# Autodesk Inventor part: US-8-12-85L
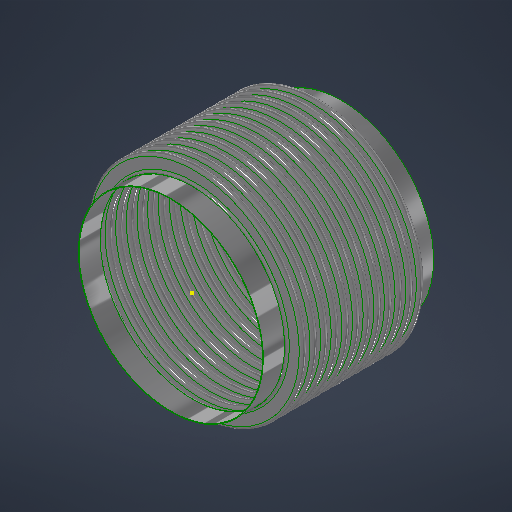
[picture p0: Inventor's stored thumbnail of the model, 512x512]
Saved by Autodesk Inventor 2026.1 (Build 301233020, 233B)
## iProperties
Category: 22 GA (0.030 THICK)
RuleStatus: InUse
Created: 2026-07
Part Number: US-8-12-85L
Project: =STOCK BELLOWS: <Stock Number><SFILL>
Material: ASTM A240-304
Description: =STOCK BELLOWS: <Stock Number>, <SID_> I.D., <SOD_> O.D., <SPLY_> PLY, <Category>, <SNET_CONS> CONS.<PITCH_><STANGENT_> TANGENT<SFILL>
Document SubType Name: Sheet Metal
Designer: LC
Stock Number: U.S-8-12-85L
Surface Area: 659.127 cm^2
Volume: 56.61 cm^3
Sheet Metal Rule: Default
Appearance: STAINLESS STEEL
NET_TUBE: 3.428
COUNTER: 1.500
PBAR: 1.214
PSET: 5.356
PLY: 2
CONS: 2
THK: 0.036
ID: 4.500
OD: 5.500
CONS_: 2
TANGENT: 0.500
PITCH: 0.375
BELLOWS_UPSET: 0.000
NET_CONS: 2
S_CONS: 0
Description_Units: 0
ID_M: 114.30 mm
OD_M: 139.70 mm
THK_M: 0.91 mm
ID_U: 4.500 in
OD_U: 5.500 in
THK_U: 0.036 in
TANGENT2: 0.500
d79: 1.000
d82: 1.000
d83: 26.000
d84: 24.000
d80: 2.571
d81: 10
SID: 2.375
SCONS_: 12
SPITCH: 0.250
SBELLOWS_UPSET: 0.000
SNET_CONS: 12
SS_CONS: 0
SCONS: 8
d174: 8
d177: 0.018
d178: 2.375
d179: 3.000
d180: 0.375
d181: 1.000
d182: 0.000
d190: 8
d191: 1
d192: 1
d193: 8
d194: 0
PART_NUMBER: U.S-8-12-85L
PRESSURE: 85
SIZE: 8.00
STANGENT_: 1.000
d214: 8
d217: 0.030
d218: 6.625
d219: 8.125
d220: 0.500
d221: 1.000
d222: 0.000
d230: 8
d231: 1
d232: 1
d233: 8
d234: 0
STANGENT: 4.000
SPLY_: 1
STHK_: 0.030
SID_: 8.625
SOD_: 10.125
SPITCH_: 0.500
STANGENT__: 1.000
SBELLOWS_UPSET_: 0.000
SDIFF_TAN: 1.000
TAN_TO_TAN: 0.750 in
d252: 2
d275: 2
d287: 0.050
d289: 0.500
d290: 0.000
d263: 2
d265: 1
d268: 2
d269: 0
d286: 2
d288: 1
d291: 2
d292: 0
SOD_NECK: 8 11/16
CFILL: .
SFILL: .
PITCH_: =, <SPITCH_> PITCH,
SREROLL: 0.750
MATTABLE: 20 GA (0.036 THICK)
MESH: ,
CSECT: 2
Author: LC
Keywords: 20 GA (0.036 THICK)
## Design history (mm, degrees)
sketch "Sketch2"
  geometry: L1 (0, -183.595)-(0, 600.956) reference; L2 (58.979, 0)-(57.15, 0); L3 (60.446, -1.467)-(66.554, -1.467); L4 (60.446, -3.296)-(66.554, -3.296); L5 (66.554, -8.058)-(60.446, -8.058); L6 (66.554, -6.229)-(60.446, -6.229); L7 (58.979, -9.525)-(57.15, -9.525); L8 (60.446, 0)-(60.446, -9.525); L9 (66.554, -4.762)-(69.85, -4.763); L10 (57.15, 0)-(57.15, -9.525); L11 (20.376, 102.841)-(20.376, 101.926); L12 (58.262, 488.877)-(58.262, 349.177); L13 (58.262, 479.352)-(58.262, 339.652); L14 (93.133, -58.817)-(93.133, -71.517); L15 (118.746, -66.401)-(118.746, -66.401); L16 (66.554, -6.229)-(66.554, -8.058); L17 (60.446, -6.229)-(60.446, -8.058); L18 (60.446, -7.144)-(66.554, -7.144); L19 (69.85, 0)-(69.85, -9.525); L20 (-66.554, -6.229)-(-66.554, -8.058); L21 (-66.554, -1.467)-(-60.446, -1.467); L22 (-66.554, -3.296)-(-60.446, -3.296); L23 (-60.446, -6.229)-(-66.554, -6.229); L24 (-66.554, -7.144)-(-60.446, -7.144); L25 (-60.446, -8.058)-(-66.554, -8.058); L26 (-60.446, -6.229)-(-60.446, -8.058); L27 (-57.15, -2.522)-(-57.15, -12.047); L28 (-60.446, -4.763)-(-57.15, -4.763); L29 (-66.554, 3.828)-(-66.554, -9.525); L30 (-68.021, 0)-(-69.85, 0); L31 (-69.85, 0)-(-69.85, -9.525); L32 (-68.021, -9.525)-(-69.85, -9.525); A1 r 1.467 centre (60.446, 0) between (58.979, 0) and (60.446, -1.467); A2 r 3.296 centre (60.446, 0) between (57.15, 0) and (60.446, -3.296); A3 r 3.296 centre (66.554, -4.762) between (66.554, -8.058) and (66.554, -1.467); A4 r 1.467 centre (66.554, -4.762) between (66.554, -6.229) and (66.554, -3.296); A5 r 1.467 centre (60.446, -9.525) between (60.446, -8.058) and (58.979, -9.525); A6 r 3.296 centre (60.446, -9.525) between (60.446, -6.229) and (57.15, -9.525); A7 r 2.381 centre (66.554, -4.762) between (66.554, -7.144) and (68.936, -4.762); A8 r 2.381 centre (60.446, -9.525) between (60.446, -7.144) and (58.064, -9.525); A9 r 1.467 centre (-66.554, -9.525) between (-66.554, -8.058) and (-68.021, -9.525); A10 r 1.467 centre (-60.446, -4.763) between (-60.446, -6.229) and (-60.446, -3.296); A11 r 2.381 centre (-60.446, -4.763) between (-60.446, -7.144) and (-58.064, -4.763); A12 r 3.296 centre (-60.446, -4.763) between (-60.446, -8.058) and (-60.446, -1.467); A13 r 2.381 centre (-66.554, -9.525) between (-66.554, -7.144) and (-68.936, -9.525); A14 r 3.296 centre (-66.554, -9.525) between (-66.554, -6.229) and (-69.85, -9.525); A15 r 1.467 centre (-66.554, 0) between (-68.021, 0) and (-66.554, -1.467); A16 r 3.296 centre (-66.554, 0) between (-69.85, 0) and (-66.554, -3.296); 10 further points
  constraints: 62 end point, 38 point on circle, 20 tangent, 16 centre point, 12 parallel, 9 midpoint, 7 vertical, 6 coincident, 6 concentric, 6 point on line, 4 equal radius, 4 perpendicular, 3 horizontal, 1 collinear, 1 horizontal alignment, 10 other
  dimensions: "THK" = 0.9144 distance of L11.start L11.end; "ID" = 114.3 distance of L11.end point (20.376, -12.374); "OD" = 139.7 distance of L12.start L12.end; "PITCH" = 9.525 distance of L12.start L13.start; "TANGENT" = 12.7 distance of L14.start L14.end; "BELLOWS_UPSET" = 0 distance of L15.start L15.end; "d43" = 114.3 diameter of L10 L1 (= ID); "d44" = 139.7 diameter of L9.end L1 (= OD); "d45" = 1.8288 distance between parallel lines of L5 L6 (computed from THK, PLY); "d46" = 3.29565 radius of A3 (computed from PITCH, THK, PLY); "UPSET_PITCH" = 9.525 distance of L2.end L7.end (derived); "SIDEWALL_ANGLE" = 0 deg angle of L3 L9 (derived); "CON_GAP" = 2.9337 distance of point (60.446, -6.229) point (60.446, -3.296) (derived); "TAN1" = 3.74046 dimension on A8 (derived); "TAN2" = 3.74046 dimension on A7 (derived); "LEG1" = 6.1087 distance of L18.start L18.end (derived); "d278" = 1.8288 distance between parallel lines of L25 L23 (derived); "d279" = 3.29565 radius of A12 (derived); "d280" = 9.525 distance of L30.end L31.end (derived); "d281" = 360 deg dimension on L21 L28 (derived); "d282" = 2.9337 distance of point (-66.554, -6.229) point (-66.554, -3.296) (derived); "d283" = 3.74046 dimension on A13 (derived); "d284" = 3.74046 dimension on A11 (derived); "d285" = 6.1087 distance of L24.start L24.end (derived); "d293" = 114.3 diameter of L27 L1 (derived); "d294" = 139.7 diameter of L31 L1 (derived)
  node "Sketch Rectangular Pattern1" dims "d31" = 25.4, "ID" = 114.3
  node "Sketch Rectangular Pattern2" dims "d39" = 25.4, "PITCH" = 9.525
revolve "CONS" stored, may be unused: angle "d48" = 90 deg
node "BELLOW MIDPLANE"
pattern_linear "Rectangular Pattern2" dims "d52" = 9.525 (= UPSET_PITCH)
sketch "Sketch5"
  geometry: C1 r 58.979 at (0, 0) reference; C2 r 57.15 at (0, 0) reference
extrude "TANGENT" new body sketch "Sketch5" distance "d53" = 12.7 (= TANGENT); taper "d54" = 0 deg
revolve "SAMETAN" stored, may be unused: angle "d65" = 90 deg
revolve "DIFFTAN" stored, may be unused: angle "d70" = 90 deg
sketch "Sketch9"
  geometry: L1 (58.391, 0)-(-58.391, 0) reference; L2 (0, -17.78)-(0, 17.78) reference; L3 (41.708, 0)-(-41.708, 0); L4 (41.708, -11.906)-(41.708, 11.906); L5 (29.008, -11.906)-(29.008, 11.906); L6 (15.418, 11.906)-(15.418, -11.906); L7 (-29.008, -11.906)-(-29.008, 11.906); L8 (-41.708, -11.906)-(-41.708, 11.906); L9 (40.914, -11.906)-(40.914, 11.906); L10 (41.708, -11.906)-(40.914, -11.906); L11 (41.708, 11.906)-(40.914, 11.906); L12 (15.815, 11.906)-(15.022, 11.906); L13 (15.022, 11.906)-(15.022, -11.906); L14 (15.022, -11.906)-(15.815, -11.906); L15 (15.815, -11.906)-(15.815, 11.906); L16 (-15.815, 11.906)-(-15.815, -11.906); L17 (-15.418, 11.906)-(-15.418, -11.906); L18 (-15.815, -11.906)-(-15.022, -11.906); L19 (-15.022, -11.906)-(-15.022, 11.906); L20 (-15.022, 11.906)-(-15.815, 11.906); L21 (-41.708, -11.906)-(-40.914, -11.906); L22 (-40.914, -11.906)-(-40.914, 11.906); L23 (-40.914, 11.906)-(-41.708, 11.906); L24 (-41.708, 11.906)-(-41.708, -11.906); L25 (41.708, -0.397)-(-41.708, -0.397); L26 (-41.708, -0.397)-(-41.708, 0.397); L27 (-41.708, 0.397)-(41.708, 0.397); L28 (41.708, 0.397)-(41.708, -0.397); L29 (-41.708, 11.906)-(41.708, 11.906); L30 (41.708, 11.906)-(41.708, 12.7); L31 (41.708, 12.7)-(-41.708, 12.7); L32 (-41.708, 12.7)-(-41.708, 11.906); L33 (41.708, -11.906)-(-41.708, -11.906); L34 (-41.708, -11.906)-(-41.708, -12.7); L35 (-41.708, -12.7)-(41.708, -12.7); L36 (41.708, -12.7)-(41.708, -11.906); 30 further points
  constraints: 68 end point, 13 midpoint, 13 parallel, 8 horizontal, 7 perpendicular, 6 equal length, 3 point on line, 2 vertical, 14 other
  dimensions: "d115" = 23.8125 distance of L4.start L4.end (derived); "d116" = 12.7 distance between parallel lines of L4 L5 (derived); "d117" = 13.58962 distance between parallel lines of L5 L6 (derived); "d125" = 44.42645 distance between parallel lines of L7 L6 (derived); "d127" = 12.7 distance between parallel lines of L8 L7 (derived); "d128" = 26.28962 distance between parallel lines of L6 L4 (derived); "d130" = 83.41607 distance between parallel lines of L8 L4 (derived); "RULER_THK" = 0.79375 distance between parallel lines of L4 L9; "d135" = 0.79375 distance of L13.end L14.end (derived); "d138" = 30.83684 distance of L13.end L16.end (derived); "d143" = 0.79375 distance of L22.end L8.end (derived); "d144" = 0.79375 distance between parallel lines of L27 L25 (derived)
extrude "RULER" join sketch "Sketch9" distance "d149" = 0.79375 (derived); taper "d150" = 0 deg
extrude "BARS" join sketch "Sketch9" distance "d151" = 0.79375 (derived); taper "d152" = 0 deg
pattern_linear "Rectangular Pattern4" dims "d155" = 30.83684 (derived)
sketch "Sketch13"
  geometry: L1 (93.149, -52.467)-(93.149, -77.867); L2 (110.299, 0)-(109.537, 0); L3 (110.299, -12.7)-(109.537, -12.7); L4 (125.031, -9.906)-(113.093, -9.906); L5 (125.032, -9.144)-(113.094, -9.144); L6 (125.031, -6.35)-(128.588, -6.35); L7 (113.094, -2.794)-(125.031, -2.794); L8 (113.094, 0)-(113.093, -12.7); L9 (109.537, 0)-(109.537, -12.7); L10 (58.254, -312.281)-(58.254, -569.456); L11 (58.254, -324.981)-(58.254, -582.156); L12 (58.254, -350.381)-(58.254, -607.556); L13 (58.254, -363.081)-(58.254, -620.256); L14 (58.254, -375.781)-(58.254, -632.956); L15 (58.254, -388.481)-(58.254, -645.656); L16 (58.254, -401.181)-(58.254, -658.356); L17 (58.254, -337.681)-(58.254, -594.856); L18 (20.376, 102.688)-(20.376, 101.926); L19 (113.094, -3.556)-(125.031, -3.556); L20 (0, -769.925)-(0, 248.124) reference; L21 (-23.752, 0)-(142.514, 0) reference; A1 r 2.794 centre (113.094, 0) between (110.299, 0) and (113.094, -2.794); A2 r 2.794 centre (113.093, -12.7) between (113.093, -9.906) and (110.299, -12.7); A3 r 3.556 centre (113.093, -12.7) between (113.094, -9.144) and (109.537, -12.7); A4 r 2.794 centre (125.031, -6.35) between (125.032, -9.144) and (125.031, -3.556); A5 r 3.556 centre (125.031, -6.35) between (125.031, -9.906) and (125.031, -2.794); A6 r 3.556 centre (113.094, 0) between (109.537, 0) and (113.094, -3.556); 6 further points; 1 other entity
  constraints: 38 end point, 15 point on circle, 9 tangent, 6 centre point, 6 parallel, 5 vertical alignment, 4 point on line, 4 vertical, 3 coincident, 3 concentric, 2 collinear, 2 equal radius, 1 horizontal, 1 perpendicular, 23 other
  dimensions: "SBELLOWS_UPSET_" = 0 distance of point (118.762, -66.401) point (118.762, -66.401); "STOTAL_THK_BELLOW__" = 0.762 distance between parallel lines of L4 L5 (derived); "d224" = 3.556 radius of A5 (derived); "d225" = 12.7 distance of L2.end L3.end (derived); "SSIDEWALL_ANGLE_" = 0 deg angle of L7 L6 (derived); "SSCON_GAP_" = 5.588 distance of point (113.094, -9.144) point (113.094, -3.556) (derived); "d235" = 219.075 diameter of L9 L20 (derived); "d236" = 257.175 diameter of L6.end L20 (derived)
  node "Sketch Rectangular Pattern4" dims "d228" = 25.4
  node "Sketch Rectangular Pattern5" dims "d229" = 25.4
revolve "SBELLOW" stored, may be unused: angle "d197" = 90 deg
pattern_linear "Rectangular Pattern5" dims "d204" = 12.7 (derived)
revolve "STANGENT" stored, may be unused: angle "d240" = 90 deg
revolve "SSAMETAN" stored, may be unused: angle "d241" = 90 deg
revolve "SDIFFTAN" stored, may be unused: angle "d246" = 90 deg
revolve "INVCON" stored, may be unused: angle "d295" = 90 deg
pattern_linear "Rectangular Pattern6" dims "d298" = 9.525 (derived)
revolve "INVTANGENT" stored, may be unused: angle "d302" = 90 deg
revolve "INVSAMETAN" stored, may be unused: angle "d307" = 90 deg
revolve "INVDIFFTAN" stored, may be unused: angle "d312" = 90 deg
sketch "ID BELLOW MOUNT CALC"
  geometry: L1 (44.45, 0)-(38.1, 0); L2 (38.1, 0)-(38.1, 12.7); L3 (38.1, 12.7)-(44.45, 12.7); L4 (44.45, 12.7)-(44.45, 0); L5 (36.513, 12.7)-(34.684, 12.7); L6 (34.684, 12.7)-(34.684, 0); L7 (34.684, 0)-(36.513, 0); L8 (36.513, 0)-(36.513, 12.7); L9 (0, -2.54)-(0, 15.24) reference; L10 (-8.89, 0)-(53.34, 0) reference; 1 further point
  constraints: 16 end point, 5 parallel, 2 collinear, 2 horizontal, 2 perpendicular
  dimensions: "d314" = 12.7 distance of L5.end L6.end (derived); "d315" = 1.8288 distance of L5.start L5.end (derived); "IG" = 1.5875 distance between parallel lines of L2 L8; "PIPE_OD" = 88.9 diameter of L4 L9; "PIPE_WALL" = 6.35 distance of L2.end L3.end; "ID_MT_BELLOW" = 69.3674 diameter of L6 L9 (derived)
revolve "CFILL" stored, may be unused: angle "d320" = 90 deg
pattern_linear "Rectangular Pattern7" dims "d323" = 9.525 (derived)
revolve "SFILL" stored, may be unused: angle "d324" = 90 deg
pattern_linear "Rectangular Pattern8" dims "d327" = 12.7 (derived)
node "STOCK BELLOW MIDPLANE"
sketch "Sketch21"
  geometry: L1 (0, -100.013)-(0, 100.013) reference; L2 (-100.013, 0)-(100.013, 0) reference; L3 (-0.099, 71.437)-(0.099, 71.437); L4 (0.099, 71.437)-(0.099, 55.562); L5 (0.099, 55.562)-(-0.099, 55.562); L6 (-0.099, 55.562)-(-0.099, 71.437); C1 r 55.562 at (0, 0); C2 r 71.437 at (0, 0); 3 further points
  constraints: 8 end point, 2 centre point, 2 coincident, 2 parallel, 2 tangent, 1 horizontal, 1 perpendicular, 1 other
  dimensions: "d329" = 111.125 diameter of C1 (derived); "d330" = 142.875 diameter of C2 (derived); "d331" = 0.19844 distance of L3.start L3.end
extrude "CLAMSHELL" cut sketch "Sketch21" extent not by distance; stored distance "d332" = 0; taper "d333" = 0 deg
pattern_circular "Circular Pattern1" dims angle "d335" = 180 deg (derived)
node "BELLOW"
sketch "Sketch6"
  geometry: L1 (-19.05, 58.979)-(-6.35, 58.979); L2 (-6.35, 58.979)-(-6.35, 57.15); L3 (-6.35, 57.15)-(-19.05, 57.15); L4 (-19.05, 57.15)-(-19.05, 58.979); L5 (2.54, 0)-(-59.69, 0) reference; L6 (-38.1, -108.388)-(-38.1, 156.601) reference; 1 further point
  constraints: 8 end point, 2 parallel, 1 horizontal, 1 perpendicular
  dimensions: "d61" = 12.7 distance of L2.end L3.end (derived); "d62" = 1.8288 distance of L1.end L2.end (derived); "d63" = 114.3 diameter of L3 L5 (derived); "d64" = 19.05 distance between parallel lines of L4 L6 (derived)
sketch "Sketch12"
  geometry: 1 further point
sketch "Sketch14"
  geometry: L1 (-25.4, 110.299)-(0, 110.299); L2 (0, 110.299)-(0, 109.537); L3 (0, 109.537)-(-25.4, 109.537); L4 (-25.4, 109.537)-(-25.4, 110.299); L5 (5.08, 0)-(-30.48, 0) reference; L6 (0, -16.98)-(0, 101.879) reference; 1 further point
  constraints: 8 end point, 2 parallel, 1 collinear, 1 horizontal, 1 perpendicular
  dimensions: "d237" = 0.762 distance of L3.end L1.start (derived); "d238" = 219.075 diameter of L3 L5 (derived); "d239" = 25.4 distance of L1.start L1.end (derived); "SOD_NECK" = 220.599 diameter of L1 L5 (derived)
sketch "Sketch15"
  geometry: L1 (-16.98, 0)-(101.879, 0) reference; L2 (109.538, -152.4)-(110.299, -152.4); L3 (110.299, -152.4)-(110.299, -177.8); L4 (110.299, -177.8)-(109.537, -177.8); L5 (109.537, -177.8)-(109.538, -152.4); L6 (0, -215.9)-(0, 50.8) reference; 1 further point
  constraints: 8 end point, 2 parallel, 1 horizontal, 1 perpendicular
  dimensions: "d205" = 25.4 distance of L4.end L2.start (derived); "d206" = 0.762 distance of L3.end L4.end (derived); "d207" = 219.075 diameter of L5 L6 (derived); "d208" = 152.4 distance between parallel lines of L1 L2 (derived)
node "TANGENT_"
node "SAME_TAN"
sketch "Sketch8"
  geometry: L1 (58.979, -19.05)-(57.15, -19.05); L2 (57.15, -19.05)-(57.15, -31.75); L3 (57.15, -31.75)-(58.979, -31.75); L4 (58.979, -31.75)-(58.979, -19.05); L5 (0, -40.64)-(0, 21.59) reference; L6 (-108.388, 0)-(156.601, 0) reference; 1 further point
  constraints: 8 end point, 2 parallel, 1 horizontal, 1 perpendicular
  dimensions: "d66" = 114.3 diameter of L2 L5 (derived); "TOTAL_THK_BELLOW" = 1.8288 distance of L2.end L3.end (derived); "d68" = 19.05 distance between parallel lines of L1 L6 (derived); "d69" = 12.7 distance of L1.end L2.end (derived)
node "DIFF_TAN"
node "Sketch Rectangular Pattern3" dims "d138" = 30.83684 (derived), "d141" = 25.4
node "SBELLOW_"
node "STANGENT_"
node "SSAME_TAN"
sketch "Sketch16"
  geometry: L1 (110.299, -152.4)-(109.537, -152.4); L2 (109.537, -152.4)-(109.537, -177.8); L3 (109.537, -177.8)-(110.299, -177.8); L4 (110.299, -177.8)-(110.299, -152.4); L5 (0, -215.9)-(0, 50.8) reference; L6 (-16.98, 0)-(101.879, 0) reference; 1 further point
  constraints: 8 end point, 2 parallel, 1 horizontal, 1 perpendicular
  dimensions: "SDIFF_TAN" = 25.4 distance of L3.end L1.start; "d243" = 0.762 distance of L2.end L3.end (derived); "d244" = 152.4 distance between parallel lines of L1 L6 (derived); "d245" = 219.075 diameter of L2 L5 (derived)
node "SDIFF_TAN"
body "Solid15"
sketch "Sketch17"
  geometry: L1 (69.85, 12.7)-(68.021, 12.7); L2 (68.021, 12.7)-(68.021, 0); L3 (68.021, 0)-(69.85, 0); L4 (69.85, 0)-(69.85, 12.7); L5 (0, -2.54)-(0, 15.24) reference; L6 (-13.97, 0)-(83.82, 0) reference; 2 further points
  constraints: 8 end point, 2 parallel, 1 horizontal, 1 midpoint, 1 perpendicular, 1 point on line
  dimensions: "INVTANGENT" = 12.7 distance of L3.end L1.start (derived); "d300" = 1.8288 distance of L1.start L1.end (derived); "d301" = 139.7 diameter of L4 L5 (derived)
body "Solid16"
sketch "Sketch18"
  geometry: L1 (69.85, -19.05)-(68.021, -19.05); L2 (68.021, -19.05)-(68.021, -31.75); L3 (68.021, -31.75)-(69.85, -31.75); L4 (69.85, -31.75)-(69.85, -19.05); L5 (-13.97, 0)-(83.82, 0) reference; L6 (0, -40.64)-(0, 21.59) reference; 1 further point
  constraints: 8 end point, 2 parallel, 1 horizontal, 1 perpendicular
  dimensions: "d303" = 19.05 distance between parallel lines of L1 L5 (derived); "d304" = 12.7 distance of L3.end L1.start (derived); "d305" = 1.8288 distance of L2.end L3.end (derived); "d306" = 139.7 diameter of L4 L6 (derived)
body "Solid17"
sketch "Sketch19"
  geometry: L1 (69.85, -19.05)-(68.021, -19.05); L2 (68.021, -19.05)-(68.021, -31.75); L3 (68.021, -31.75)-(69.85, -31.75); L4 (69.85, -31.75)-(69.85, -19.05); L5 (0, -40.64)-(0, 21.59) reference; L6 (-13.97, 0)-(83.82, 0) reference; 1 further point
  constraints: 8 end point, 2 parallel, 1 horizontal, 1 perpendicular
  dimensions: "d308" = 12.7 distance of L1.end L2.end (derived); "d309" = 139.7 diameter of L4 L5 (derived); "d310" = 1.8288 distance of L2.end L3.end (derived); "d311" = 19.05 distance between parallel lines of L1 L6 (derived)
body "Solid18"
body "Solid19"
body "Solid20"
other parameters: "BMPL" = -76.2, "PSET" = 136.0424 (computed from OD, THK, PLY) [user parameter], "PBAR" = 30.83684 (= 0.570796 x PITCH + OD - ID) [user parameter; used in 1 equation term], "COUNTER" = 15 [user parameter], "NET_TUBE" = 87.07367 (computed from CONS_, PBAR, TANGENT) [user parameter], "S_CONS" = 0 [user parameter; used in 1 equation term], "ID_M" = 114.3 (= ID) [user parameter], "OD_M" = 139.7 (= OD) [user parameter], "THK_M" = 0.9144 (= THK) [user parameter], "ID_U" = 114.3 (= ID) [user parameter], "OD_U" = 139.7 (= OD) [user parameter], "THK_U" = 0.9144 (= THK) [user parameter], "D_UNITS" = 0 [user parameter], "TANGENT2" = 12.7 [user parameter], "TAN_TO_TAN" = 19.05 [user parameter], "OD_NECK" = 117.9576 [user parameter], "d79" = 25.4, "d80" = 65.29823 [user parameter], "d82" = 25.4, "d83" = 660.4, "d84" = 609.6, "sa_0" = 4, "FRAME_THK" = 0.79375 [user parameter], "CON_FLAT" = 13.58962 [user parameter], "SID" = 60.325 [user parameter], "SPITCH" = 6.35 [user parameter], "STANGENT_" = 25.4 [user parameter], "SBELLOWS_UPSET" = 0 [user parameter], "SS_CONS" = 0 [user parameter], "STAN_TO_TAN_" = 152.4 [user parameter], "d100" = 0.762 [user parameter], "d191" = 25.4 [user parameter], "d194" = 0 [user parameter], "STANGENT" = 101.6 [user parameter], "d234" = 0 [user parameter], "SUPSET_PITCH_" = 12.7 [user parameter], "d269" = 0 [user parameter], "d287" = 1.27, "d289" = 12.7, "d290" = 0, "d292" = 0 [user parameter], "Thickness" = 3.048 (derived), "KFactor" = 4.4, "BendRadius" = 3.048 (derived), "BendReliefWidth" = 3.048 (derived), "BendReliefDepth" = 1.524 (derived), "CornerReliefSize" = 12.192 (derived), "SeamGap" = 0.00508, "MinimumRemnant" = 6.096 (derived), "TransitionRadius" = 3.048 (derived), "JacobiRadiusSize" = 3.048 (derived), "GapSize" = 3.048 (derived), "SREROLL" = 19.05 [user parameter], "CUR_STK_PITCH" = 12.7 [user parameter], "d328" = -76.2 (derived), "CSECTDEG" = 180 deg [user parameter]
